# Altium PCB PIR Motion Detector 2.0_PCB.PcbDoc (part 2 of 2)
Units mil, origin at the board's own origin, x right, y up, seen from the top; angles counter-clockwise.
Board outline 6000 x 2200 mil, 4 copper layers (Layer 1 - Top Layer, Layer 2 - GND, Layer 3 - PWR, Layer 4 - Bottom Layer), stack 61.634 mil thick; 136 components, 49 nets, 322 pads, 287 vias.
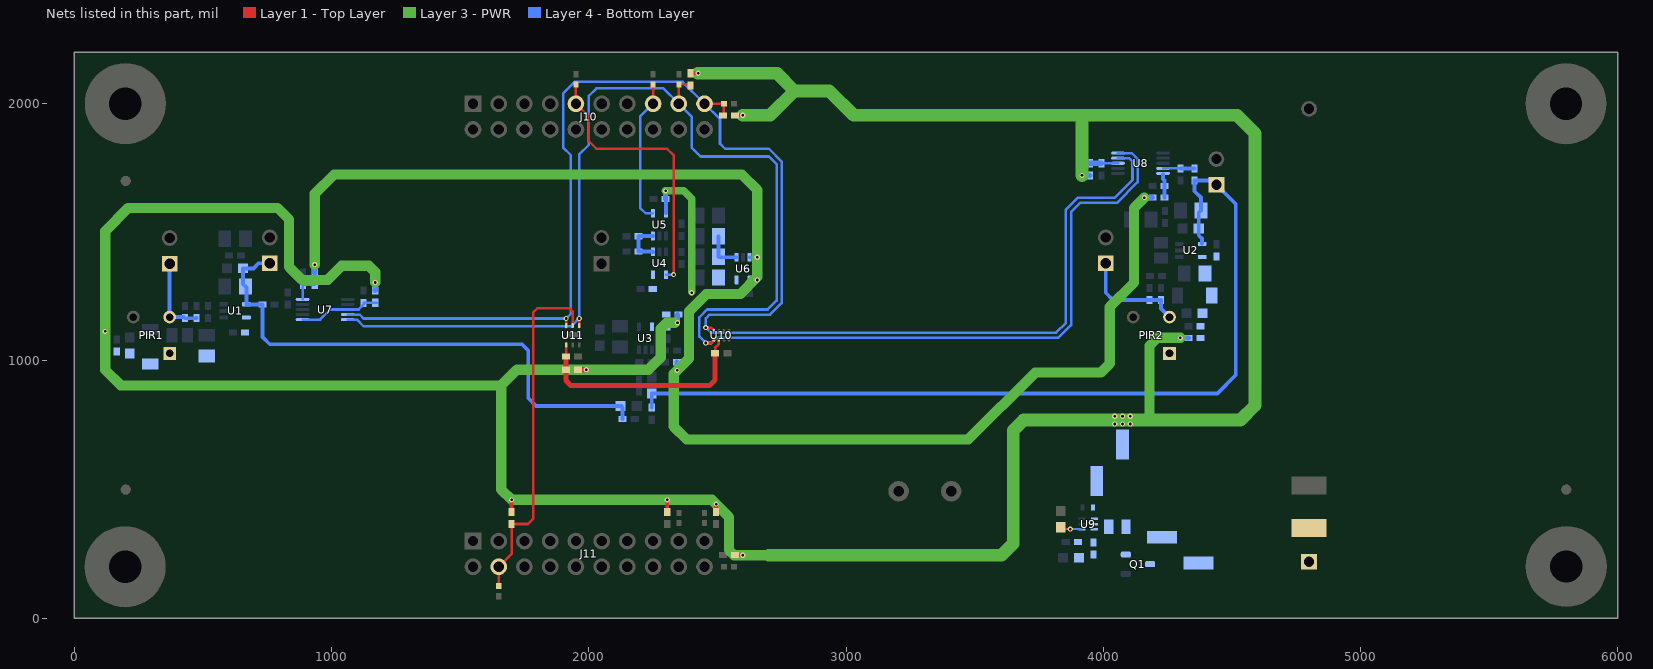
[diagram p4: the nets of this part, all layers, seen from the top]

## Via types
v1: diameter 20, hole 10, Layer 1 - Top Layer to Layer 4 - Bottom Layer, tented both sides, 286 vias
v2: diameter 19.68, hole 7.87, Layer 1 - Top Layer to Layer 4 - Bottom Layer, 1 vias

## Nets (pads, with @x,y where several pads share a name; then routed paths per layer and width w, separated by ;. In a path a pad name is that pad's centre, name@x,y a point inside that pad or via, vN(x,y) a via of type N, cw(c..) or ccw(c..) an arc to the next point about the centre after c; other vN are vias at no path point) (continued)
NetC14_1: C14.1 R23.2 U7.5 | length 102.6
  Layer 4 - Bottom Layer w10: U7.5@887.4,1239.37 887.4,1293.74 C14.1@889.67,1296.01 R23.2@934.67,1296.01
NetC15_1: C15.1 R24.2 U8.4 | length 122.6
  Layer 4 - Bottom Layer w10: U8.4@4232.56,1748.92 4232.85,1748.62 C15.1@4300,1748.62
  Layer 4 - Bottom Layer w15: C15.1@4300,1748.62 R24.2@4355,1748.62
NetC16_1: C16.1 R25.2 U8.5 | length 93.5
  Layer 4 - Bottom Layer w15: U8.5@4232.56,1726 4232.56,1707.44 4238.62,1701.38 C16.1@4238.62,1680 R25.2@4238.62,1635
NetC18_1: C18.1 R26.2 U9.3
NetC19_1: C19.1 J7.1 U9.1
NetC36_1: C36.1 R17.2 U4.1 U5.3 | length 172.2
  Layer 4 - Bottom Layer w15: U4.1@2249.41,1424.29 2248.7,1425 R17.2@2193.62,1425 C36.1@2193.62,1485 2194.33,1485.71 U5.3@2249.41,1485.71
NetJ1_1: J1.1 PIR1.2 R1.2 R2.1 | length 313.4
  Layer 4 - Bottom Layer w15: J1.1@370.57,1377.95 370.57,1170.85 PIR1.2@370.71,1170.71 425.67,1170.71 R1.2@430,1166.38 R2.1@475,1166.38
NetJ2_1: J2.1 PIR2.2 R7.2 R8.1 | length 421.1
  Layer 4 - Bottom Layer w15: J2.1@4010,1380 4010,1265 4038.62,1236.38 R8.1@4180,1236.38 R7.2@4225,1236.38 4225,1203.42 PIR2.2@4257.71,1170.71
NetJ6_2: J6.2 Q1.3
NetL1_2: L1.2 U9.2
NetR19_1: R19.1 R20.2 U6.1 | length 150.1
  Layer 4 - Bottom Layer w15: R20.2@2505,1485 R19.1@2505,1405 2506.56,1403.44 U6.1@2574.41,1403.44
NetR39_2: R39.2 U9.4 | length 85.9
  Layer 1 - Top Layer w8: R39.2@3835,353.5 3842.04,346.47 v1(3872.04,346.47)
  Layer 4 - Bottom Layer w8: v1(3872.04,346.47) U9.4@3917.99,346.47
OPT3002_INT: J11.4 R38.1 U11.5 U19.1 | length 1377.4
  Layer 1 - Top Layer w10: U19.1@1650,124.68 J11.4@1650,200 1700,250 R38.1@1700,366.38 1763.62,366.38 1785,387.76 1785,1190 1800,1205 1925,1205 1937.34,1192.66 U11.5@1937.34,1137.4
P3.3V: J7.2 R27.1 R28.1 R29.1 R30.1 R31.1 R32.1 R33.2 R34.2 R35.2 R36.2 R37.2 R38.2 | length 12934.7
  Layer 1 - Top Layer w15: R38.2@1700,413.62 v1(1700,460) ; R35.2@2305,413.62 v1(2305,460) ; R34.2@2395,2118.62 v1(2425,2118.62) ; R36.2@2495,413.62 v1(2495,443.62) ; R37.2@2568.62,245 v1(2598.62,245) ; R33.2@2568.62,1955 v1(2598.62,1955)
  Layer 1 - Top Layer w20: R32.1@1958.62,965.78 v1(1990,965.78)
  Layer 3 - PWR w40: v1(1170,1305) 1170,1345 1145,1370 1040,1370 985,1315 885,1315 835,1365 835,1550 790,1595 210,1595 120,1505 v1(120,1115) 120,965 180,905 1660,905 ; v1@2335,1148.62 2303.62,1148.62 2280,1125 2280,1015 2230.78,965.78 v1(1990,965.78) 1720.78,965.78 1660,905 ; 2700,245 v1(2598.62,245) 2565,245 2545,265 2545,393.62 v1(2495,443.62) 2478.62,460 v1(2305,460) v1(1700,460) 1660,500 1660,905 ; 4180,795 4180,1060 4210,1090 v1(4300,1090)
  Layer 3 - PWR w50: v1(2425,2118.62) 2731.38,2118.62 2800,2050 ; v1(2598.62,1955) 2705,1955 2800,2050 ; 2700,245 3605,245 3650,290 3650,730 3690,770 4533,770 4590,827 4590,1885 4520,1955 3030,1955 2935,2050 2800,2050 ; v1(3917.4,1721.38) 3917.4,1952.4
  Layer 4 - Bottom Layer w20: R27.1@120,1083.62 v1(120,1115) ; R28.1@1170,1273.62 v1(1170,1305) ; v1(2345,1148.62) R31.1@2345,1180 ; v1(3917.4,1721.38) R30.1@3948.78,1721.38 ; v1(4300,1090) R29.1@4331.38,1090
  other v1: 4045,755 4075,755 4105,755 4045,785 4075,785 4105,785
PIR1_OUT: C2.1 C4.2 J3.1 R5.2 R22.1 R40.2 U1.4 | length 2113.5
  Layer 4 - Bottom Layer w15: J3.1@760,1380 716.18,1380 696.18,1360 C2.1@656.5,1360 656.5,1298.5 R5.2@665,1290 669.29,1285.71 U1.4@669.29,1220.59 669.88,1220 R22.1@731.38,1220 731.38,1093.62 760,1065 1740,1065 1765,1040 1765,855 1794.53,825.47 C4.2@2126.95,825.47 ; C4.2@2123.5,825 2131.38,817.13 R40.2@2131.38,775
PIR2_OUT: C6.1 C8.2 J4.1 R11.2 R24.1 R41.2 U2.4 | length 3482.3
  Layer 4 - Bottom Layer w15: R41.2@2245,818.62 C8.2@2245,873.5 4443.5,873.5 4515,945 4515,1610 J4.1@4440,1685 4423.62,1701.38 R24.1@4355,1701.38 4355,1660 4380,1635 R11.2@4380,1585 4371.5,1576.5 C6.1@4371.5,1515 4371.5,1488.5 4384.29,1475.71 U2.4@4384.29,1455.59
PIR_OUT_HI: J10.9 U4.4 U21.1 | length 1087.5
  Layer 1 - Top Layer w10: U21.1@1950,2075.32 J10.9@1950,2000 2000,1950 2000,1855 2030,1825 2305,1825 2330,1800 v1(2330,1335.71)
  Layer 4 - Bottom Layer w10: U4.4@2300.59,1335.71 v1(2330,1335.71)
PIR_OUT_LO: J10.15 U5.4 U22.1 | length 559
  Layer 1 - Top Layer w10: J10.15@2250,2000 U22.1@2250,2075.32
  Layer 4 - Bottom Layer w10: U5.4@2249.41,1574.29 2220.71,1574.29 2200,1595 2200,1950 J10.15@2250,2000
SCL: J10.17 R34.1 U7.10 U8.10 U10.A1 U11.4 U15.1 | length 6267.3
  Layer 1 - Top Layer w10: U11.4@1962.93,1132 U11.4@1962.93,1137.4 v1(1962.93,1165) ; J10.17@2350,2000 U15.1@2350,2075.32 2391.06,2075.32 R34.1@2395,2071.38 ; v1(2455,1070) 2475.95,1070 U10.A1@2486.26,1080.32
  Layer 4 - Bottom Layer w10: U7.10@1062.6,1160.63 1099.37,1160.63 1125,1135 1932.93,1135 v1(1962.93,1165) 1962.93,1802.93 2000,1840 2000,2030 2029.84,2059.84 2290.16,2059.84 J10.17@2350,2000 2400,1950 2400,1830 2435,1795 2700,1795 2730,1765 2730,1235 2695,1200 2460,1200 2430,1170 2430,1095 v1(2455,1070) 2475.95,1070 2495.95,1090 3825,1090 3875,1140 3875,1580 3910,1615 4053.28,1615 4133.78,1695.5 4133.78,1785 4110.8,1807.98 U8.10@4057.36,1807.98
SDA: J10.19 R33.1 U7.9 U8.9 U10.A2 U11.6 U14.1 | length 6202.3
  Layer 1 - Top Layer w10: U11.6@1911.75,1132 U11.6@1911.75,1137.4 v1(1911.75,1165) ; J10.19@2450,2000 U14.1@2525.32,2000 2525.32,1958.94 R33.1@2521.38,1955 ; v1(2455,1130) 2475.95,1130 U10.A2@2486.26,1119.69
  Layer 4 - Bottom Layer w10: U7.9@1062.6,1180.32 1109.68,1180.32 1125,1165 v1(1911.75,1165) 1930,1183.25 1930,1800 1900,1830 1900,2039.84 1945.16,2085 2365,2085 J10.19@2450,2000 2510.04,1939.96 2510.04,1844.96 2530,1825 2700,1825 2750,1775 2750,1225 2705,1180 2470,1180 2455,1165 v1(2455,1130) 2475,1110 3816.72,1110 3855,1148.28 3855,1588.28 3901.72,1635 4045,1635 4113.78,1703.78 4113.78,1775 4100.49,1788.29 U8.9@4057.36,1788.29
VBAT: C17.1 L1.1 Q1.2 R26.1
VCC: BT1.1 J6.1 TP1.1
VCC1A: C20.1 C21.1 C22.1 C23.1 PIR1.1 R3.2 R27.2 U1.5
VCC1B: C24.1 R28.2 U7.1 U7.8 | length 318.2
  Layer 4 - Bottom Layer w10: U7.1@887.4,1160.63 955.63,1160.63 995,1200 U7.8@1062.6,1200 1105,1200 1125,1220 C24.1@1125,1226.01 R28.2@1175,1226.01
VCC2A: C25.1 C26.1 C27.1 C28.1 PIR2.1 R9.2 R29.2 U2.5
VCC2B: C29.1 R30.2 U8.8 | length 108.6
  Layer 4 - Bottom Layer w10: C29.1@3993.78,1768.62 U8.8@4057.36,1768.61
  Layer 4 - Bottom Layer w20: R30.2@3948.78,1768.62 C29.1@3993.78,1768.62
VCC3: C30.1 C31.1 C32.1 C33.1 R18.2 R31.2 U3.5 U4.5 U5.5 U6.5 | length 559.5
  Layer 3 - PWR w30: v1(2298.62,1661.38) 2368.62,1661.38 2400,1630 v1@2400,1270
  Layer 4 - Bottom Layer w15: U5.5@2300.59,1574.29 C31.1@2300.59,1628.03
  Layer 4 - Bottom Layer w20: C31.1@2298.62,1630 v1(2298.62,1661.38)
  other v1: 2400,1265
VCC4: C34.1 C35.1 R32.2 U10.B1 U11.1 | length 898.3
  Layer 1 - Top Layer w10: C34.1@1911.75,1020 U11.1@1911.75,1062.6 U11.1@1911.75,1068 ; C35.1@2491.38,1030 2491.38,1051.88 2505.95,1066.45 U10.B1@2505.95,1080.32
  Layer 1 - Top Layer w20: C34.1@1910.96,1017.21 1911.38,1016.79 R32.2@1911.38,965.78 1911.38,923.62 1930,905 2470,905 2491.38,926.38 C35.1@2491.38,1030
VREF: R16.1 R23.1 R25.1 U6.3 U6.4 | length 5874.8
  Layer 3 - PWR w40: v1(934.67,1374.63) 934.67,1649.67 1010,1725 2595,1725 2655,1665 v1(2655,1403.44) 2655,1326.65 2588.35,1260 2457,1260 2390,1193 2390,1010 2330,950 2330,745 2380,695 3475,695 3735,955 3990,955 4025,990 4025,1210 4120,1305 4120,1595 v1(4160,1635)
  Layer 4 - Bottom Layer w15: U6.4@2625.59,1314.86 v1(2655,1314.86) ; U6.3@2625.59,1403.44 v1(2655,1403.44)
  Layer 4 - Bottom Layer w20: R23.1@934.67,1343.25 v1(934.67,1374.63) ; v1(2343.62,963.62) R16.1@2343.62,995 ; v1(4160,1635) R25.1@4191.38,1635
pads on no net: FID1.1 FID2.1 FID3.1 FID4.1 FID5.1 FID6.1 H1.1 H2.1 H3.1 H4.1 J10.1 J10.2 J10.3 J10.5 J10.6 J10.7 J10.8 J10.10 J10.11 J10.12 J10.13 J10.14 J10.16 J10.18 J10.20 J11.1 J11.3 J11.5 J11.6 J11.7 J11.8 J11.9 J11.10 J11.11 J11.12 J11.13 J11.14 J11.15 J11.16 J11.18 U7.6 U7.7 U8.6 U8.7 U9.5 U10.C2

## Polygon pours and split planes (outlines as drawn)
GND on Layer 1 - Top Layer "Layer 1 - Top Layer - GND" (solid, remove dead copper, pour order 0): 20,20 5980,20 5980,2180 20,2180
GND on Layer 2 - GND "Layer 2 - GND" (solid, remove dead copper, pour order 2): 20,20 5980,20 5980,2180 20,2180
GND on Layer 3 - PWR "Layer 3 - PWR - GND" (solid, remove dead copper, pour order 4): 20,20 5980,20 5980,2180 20,2180
GND on Layer 4 - Bottom Layer "Layer 4 - Bottom Layer - GND" (solid, remove dead copper, pour order 6): 20,20 5980,20 5980,2180 20,2180

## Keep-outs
Keep-Out Layer:
  text ".Layer_Name" at 577,-858.49 h60

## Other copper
Layer 1 - Top Layer:
  pour cut-out: 2450,155.14 2350,155.14 2305.14,200 2305.14,255.14 2250,255.14 2250,315.32 2328.81,394.13 2450,394.13
  pour cut-out: 1605.14,200 1605.14,300 1644,300 1705,361 1788,361 1794.86,354.14 1794.86,200 1750,155.14 1650,155.14
  pour cut-out: 2350,1955.14 2405.14,1955.14 2405.14,1900 2494.86,1900 2494.86,2000 2450,2044.86 2380.86,2044.86 2350,2014
  pour cut-out: 1905.14,2000 1905.14,1900 1944,1900 2005,1839 2088,1839 2094.86,1845.86 2094.86,2000 2050,2044.86 1950,2044.86
  region net VCC: 4715,400 4715,210 4745,180 4855,180 4885,210 4885,400
  pour cut-out: 1810,990 2055,990 2055,1190 1810,1190
  pour cut-out: 2410,990 2655,990 2655,1180 2410,1180
  region net GND: 2520,1086 2520,993.13 2516.87,990 2594.61,990 2594.61,1041.39 2550,1086
  region net GND: 1928,1087 1932,1083 1932,1042 1942,1032 1942,1005 1950,997 1993.57,997 2010.57,980 2054,980 2060,986 2060,1113 1910,1113 1910,1087
  text ".Layer_Name" at 577,-858.49 h60
Layer 2 - GND:
  text ".Layer_Name" at 577,-858.49 h60
Layer 3 - PWR:
  text ".Layer_Name" at 577,-858.49 h60
Layer 4 - Bottom Layer:
  pour cut-out: 551.7,1241.42 551.7,1150.28 698.3,1150.28 698.3,1241.42
  pour cut-out: 2173.71,1014.81 2264.84,1014.81 2264.84,1161.41 2173.7,1161.41
  pour cut-out: 2228.58,1603.3 2319.72,1603.3 2319.72,1456.7 2228.58,1456.7
  pour cut-out: 2321.42,1306.7 2230.28,1306.7 2230.28,1453.3 2321.42,1453.3
  pour cut-out: 2646.42,1285.85 2555.28,1285.85 2555.28,1432.45 2646.42,1432.45
  pour cut-out: 4018.43,1707.58 4018.43,1828.61 4272,1828.61 4272,1707.58
  pour cut-out: 1095,1261.03 1095,1140 850,1140 850,1261.03
  pour cut-out: 2387.14,1855.14 2401,1869 2401,2013 2369.14,2044.86 1850,2044.86 1805.14,2000 1805.14,1900 1850,1855.14
  pour cut-out: 717.49,1422.51 702,1422.51 702,1431.5 695,1431.5 695,1417 717.49,1417
  region net GND: 155,1065 150,1070 150,1185 165,1200 315,1200 330,1185 330,1145 345,1130 400,1130 405,1125 405,1070 400,1065
  region net VCC1A: 95,1040 110,1055 625,1055 645,1075 645,1175 655,1185 690,1185 700,1175 700,985 675,960 110,960 95,975
  region net VCC: 4845,190 4825,170 4325,170 4310,185 4310,250 4330,270 4825,270 4845,250
  region net NetJ6_2: 4290,340 4290,215 4270,195 4165,195 4145,215 4145,340 4165,360 4270,360
  region net VBAT: 3880,255 3890,265 4045,265 4065,285 4065,380 4075,390 4110,390 4120,380 4120,240 4090,210 3886,210 3880,216
  region net NetC18_1: 3882,286 3890,278 3977,278 3985,286 3985,347 3980,352 3951,352 3946,347 3946,330 3937,321 3890,321 3882,313
  region net NetL1_2: 3986,372 3998,384 4041,384 4045,380 4045,330 4041,326 4001,326 3997,330 3997,349 3986,360 3951,360 3948,363 3948,369 3951,372
  region net NetC19_1: 3980,380 4010,410 4010,594 4004,600 3951,600 3945,594 3945,383 3948,380
  region net GND: 3931,380 3934,383 3934,461 3925,470 3850,470 3840,460 3840,400 3850,390 3878,390 3888,380
  region net VCC2A: 4220,1045 4235,1060 4345,1060 4360,1075 4360,1405 4380,1425 4470,1425 4490,1405 4490,995 4455,960 4235,960 4220,975
  region net GND: 2475,1530 2550,1530 2560,1540 2560,1590 2550,1600 2475,1600
  region net VCC3: 2230,1120 2235,1115 2315,1115 2320,1120 2320,1200 2340,1220 2580,1220 2595,1235 2595,1344.46 2580.31,1359.15 2479.15,1359.15 2470,1350 2470,1290 2455,1275 2285,1275 2270,1290 2270,1345 2260,1355 2240,1355 2230,1345
  region net P3.3V: 4045,800 4025,780 4025,625 4035,615 4115,615 4125,625 4125,780 4105,800
  region net GND: 4205,1295 4215,1305 4276,1305 4286,1295 4330,1295 4350,1275 4350,1125 4345,1120 4300,1120 4290,1130 4290,1140 4300,1150 4300,1185 4265,1220 4265,1250 4250,1265 4215,1265 4205,1275
  text ".Layer_Name" at 577,-858.49 h60

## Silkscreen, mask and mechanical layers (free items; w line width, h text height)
Top Overlay:
  region: 5825,1600 5825,1300 5925,1300 5925,1600
  text "'.PRJ_Number'.PCB_Rev-" at 5900,600 h108.27 r90
  text "GND" at 4943,448.03 h72.83 r90
  text "VCC" at 4943,283.03 h72.83 r90
  text ".Layer_Name" at 577,-858.49 h60
Bottom Overlay:
  text "SDA" at 2465,2165 h50 r90
  text "P.O" at 1940,2160 h50 r90
  text "P.O" at 2245,2160 h50 r90
  text "SCL" at 2365,2160 h50 r90
  text "LO" at 2285,2150 h50 r90
  text "HI" at 1980,2145 h50 r90
  text "GND" at 1665,1825 h50 r90
  text "ADC_A_2" at 2465,575 h50 r90
  text "ADC_A_1" at 2365,570 h50 r90
  text "GND" at 1565,125 h50 r90
  text "HDC" at 1665,125 h50 r90
  text "OPT" at 2465,125 h50 r90
  text ".Layer_Name" at 577,-858.49 h60
Top Paste:
  text ".Layer_Name" at 577,-858.49 h60
Bottom Paste:
  text ".Layer_Name" at 577,-858.49 h60
Top Solder:
  text ".Layer_Name" at 577,-858.49 h60
  text ".Layer_Name" at 577,-858.49 h60
Bottom Solder:
  text ".Layer_Name" at 577,-858.49 h60
Drill Guide:
  text ".Layer_Name" at 577,-858.49 h60
M1 Board Outline:
  the board outline again, w10
  text ".Layer_Name" at 577,-858.49 h60
M2 Board Dimensions:
  rectangle: 0,-275 125,-150
  rectangle: 125,-400 500,-275
  lines w7: 0,-275 1000,-275 ; 125,-400 125,-150 ; 250,-400 250,-150 ; 500,-400 500,-150 ; 750,-400 750,-150 ; 0,-400 1000,-400 1000,-150 0,-150 0,-400
  text ".Layer_Name" at 577,-858.49 h60
M3 3D STEP Top:
  text ".Layer_Name" at 577,-858.49 h60
M4 3D STEP Bottom:
  text ".Layer_Name" at 577,-858.49 h60
M5 Assembly Top:
  lines w10: -292,-930.17 6308,-930.17 ; -292,-726.83 6310,-726.83 ; -292,-523.5 -292,-1133.5 3713,-1133.5 6310,-1133.5 6310,-523.5 -291.5,-523.5 -291.5,-1133.5 1284,-1133.5 ; 2173,-1133.5 2173,-523.5 ; 3440,-726.83 3440,-523.5 ; 4280,-726.83 4280,-523.5 ; 4902,-1140 4902,-937.17
  text "COMPONENTS MARKED 'DNP' SHOULD NOT BE POPULATED." at 1153.5,-318.5 h60
  text "ASSEMBLY VARIANT:" at 1153,-434 h60
  text ".VariantName" at 2189,-434 h60
  text "PCB VIEWED FROM TOP SIDE" at -228.5,-655.67 h60
  text "BOARD #:" at 2248,-655.67 h60
  text ".PRJ_Number" at 2793.5,-655.67 h60
  text "REV:" at 3638,-655.67 h60
  text ".PCB_Rev" at 3929.5,-655.67 h60
  text "SVN REV:" at 4476,-655.67 h60
  text ".VersionControl_RevNumber" at 4982,-655.67 h60
  text "TID #:" at 2248,-859 h60
  text ".TID" at 2793.5,-859 h60
  text "PLOT NAME =" at -228.5,-1064.34 h60
  text ".plot_File_Name" at 577,-1064.34 h60
  text "GENERATED    :" at 2250,-1064.34 h60
  text ".Print_Date" at 3119.5,-1064.34 h60
  text ".Print_Time" at 3848.5,-1064.34 h60
  text "TEXAS INSTRUMENTS" at 5113,-1064.34 h60
M6 Assembly Bottom:
  lines w10: -292.5,-727.33 6309.5,-727.33 ; -290.5,-930.67 6309.5,-930.67 ; 1115.5,-1140.5 1115.5,-937.67 ; 1737.5,-727.33 1737.5,-524 ; 2577.5,-727.33 2577.5,-524 ; 3844.5,-1134 3844.5,-524 ; 4733.5,-1134 6309,-1134 6309,-524 -292.5,-524 -292.5,-1134 2304.5,-1134 6309.5,-1134 6309.5,-524
  text "COMPONENTS MARKED 'DNP' SHOULD NOT BE POPULATED." at 6102,-318 h60
  text ".VariantName" at 5058,-434 h60
  text "ASSEMBLY VARIANT:" at 6097,-434 h60
  text ".VersionControl_RevNumber" at 1035.5,-656.17 h60
  text "SVN REV:" at 1541.5,-656.17 h60
  text ".PCB_Rev" at 2088,-656.17 h60
  text "REV:" at 2379.5,-656.17 h60
  text ".PRJ_Number" at 3224,-656.17 h60
  text "BOARD #:" at 3769.5,-656.17 h60
  text "PCB VIEWED FROM BOTTOM SIDE" at 6246,-656.17 h60
  text ".TID" at 3224,-859.5 h60
  text "TID #:" at 3769.5,-859.5 h60
  text "TEXAS INSTRUMENTS" at 904.5,-1064.84 h60
  text ".Print_Time" at 2169,-1064.84 h60
  text ".Print_Date" at 2898,-1064.84 h60
  text "GENERATED    :" at 3767.5,-1064.84 h60
  text ".plot_File_Name" at 5440.5,-1064.84 h60
  text "PLOT NAME =" at 6246,-1064.84 h60
M9 Title Sheet:
  drawing of 1178 lines, arcs and shapes, not listed
  text "1" at 739.84,8036.5 h70
  text "2" at 3235.5,8036.5 h70
  text "3" at 5724.84,8036.5 h70
  text "4" at 8231.51,8036.5 h70
  text "5" at 10730.5,8036.5 h70
  text "6" at 13235.5,8036.5 h70
  text "A" at -416.5,6893.5 h70
  text "A" at 14383.5,6893.5 h70
  text "B" at -416.5,4513.5 h70
  text "B" at 14383.5,4513.5 h70
  text "C" at -416.5,2138.5 h70
  text "C" at 14383.5,2138.5 h70
  text "PROJECT TITLE:" at 11343.5,277.5 h45
  text ".PRJ_Title" at 11393.5,144.17 h70
  text "DESIGNED FOR:" at 11343.5,-23.5 h45
  text ".PRJ_Customer" at 11393.5,-163.5 h70
  text "D" at -416.5,-231.5 h70
  text "D" at 14383.5,-231.5 h70
  text "FILE NAME:" at 11343.5,-323.5 h45
  text ".PCB_File_Name_No_Path" at 11393.5,-443.5 h70
  text "Texas Instruments (TI) and/or its licensors do not warrant the accuracy or completeness of this specification" at 6374,-605.34 h45
  text "ENGINEER:" at 11343.5,-613.5 h45
  text "LAYOUT BY:" at 12848.5,-613.5 h45
  text "or any information contained therein. TI and/or its licensors do not warrant that this design will meet" at 6329.01,-718 h45
  text ".PRJ_Engineer" at 11393.5,-768.49 h70
  text "JMM" at 12856.28,-803.5 h100
  text "s  o  l  u  t  i  o  n  s" at 13714.28,-806.5 h68
  text "the specifications, will be suitable for your application or fit for any particular purpose, or will operate in" at 6329.01,-830.67 h45
  text ".Layer_Name" at 577,-858.49 h60
  text "ALTIUM DESIGNER VERSION:" at 12848.5,-923.5 h45
  text "an implementation. TI and/or its licensors do not warrant that the design is production worthy. You should" at 6329.01,-943.33 h45
  text "completely validate and test your design implementation to confirm the system functionality for your application." at 6374,-1056 h45
  text ".print_Scale" at 11393.5,-1056.83 h70
  text ".Application_BuildNumber" at 12899,-1056.83 h70
  text "1" at 739.84,-1263.5 h70
  text "2" at 3235.5,-1263.5 h70
  text "3" at 5724.84,-1263.5 h70
  text "4" at 8231.51,-1263.5 h70
  text "5" at 10730.5,-1263.5 h70
  text "6" at 13235.5,-1263.5 h70
M10 Fab Notes:
  drawing of 173 lines, arcs and shapes, not listed
  text "DESIGN INFORMATION" at 12378.02,6201 h60
  text "MIN. TRACK WIDTH:" at 11733.46,6021 h60
  text "MIL" at 12984.46,6021 h60
  text "10" at 12805,6020 h60
  text "MIN. CLEARANCE:" at 11733.46,5889 h60
  text "0.2" at 12769.7,5889 h60
  text "mm" at 12984.46,5889 h60
  text "MIN. VIA PAD SIZE:" at 11733.46,5757 h60
  text "20" at 12799.71,5757 h60
  text "MIL" at 12984.46,5757 h60
  text "0.05mm (2MIL)" at 12428.46,5615.29 h60
  text "MINIMUM ANNULAR RING" at 11404.23,5611 h60
  text "EXTERNAL" at 13136.46,5611 h60
  text "PER" at 11604.23,5493 h60
  text "IPC-D-275 CLASS 2 LEVEL C" at 11824.23,5493 h60
  text "MIL, HOLES" at 13312.46,5380.71 h60
  text "+/-" at 12920,5380 h60
  text "+/-" at 13774,5380 h60
  text "REGISTRATION TOLERANCES:" at 11404.23,5375 h60
  text "METAL" at 12604,5375 h60
  text "5" at 13180.2,5375 h60
  text "3" at 14013.2,5375 h60
  text "MIL" at 14129.46,5375 h60
  text "+/-" at 13774,5262 h60
  text "HOLE SIZE TOLERANCE (UNLESS OTHERWISE SPECIFIED):" at 11404.23,5257 h60
  text "3" at 14013.2,5257 h60
  text "MIL" at 14129.46,5257 h60
  text "MATERIAL:" at 11329.46,5047.54 h60
  text "FR-4 High Tg" at 12315.9,4907.21 h60
  text "FR-408" at 11750.46,4898.64 h60
  text "OTHER" at 13238.46,4898.64 h60
  text "X" at 12161,4895 h60
  text "62 MIL (1.6mm) +/-10%" at 12070.56,4735.92 h60
  text "THICKNESS:" at 11404.23,4731.64 h60
  text "X" at 11942.4,4731.64 h60
  text "OTHER" at 13355.46,4731.64 h60
  text "TOLERANCE:" at 11404.23,4573.64 h60
  text "X" at 12243.53,4573.64 h60
  text "ANSI IPC-6012 TYPE 3 CLASS 2" at 12430.48,4573.64 h60
  text "OTHER +/-" at 12430.46,4417.64 h60
  text "BOW & TWIST:" at 11404.23,4260.64 h60
  text "X" at 12243.53,4260.64 h60
  text "ANSI IPC-6012 TYPE 3 CLASS 2" at 12430.48,4260.64 h60
  text "OTHER +/-" at 12430.46,4102.13 h60
  text "DRILLING:" at 11329.46,3963.64 h60
  text "REFERENCE:" at 11404.23,3846.64 h60
  text "X" at 12052.46,3846.64 h60
  text "AS SHOWN" at 12239.46,3846.64 h60
  text "X" at 12953.46,3846.64 h60
  text "NC_DRILL FILES" at 13090.46,3846.64 h60
  text "PTH COPPER THICKNESS:" at 11404.23,3688.64 h60
  text "X" at 12534.46,3688.64 h60
  text "20-30 um" at 12671.46,3688.64 h60
  text "OTHER" at 13388.46,3688.64 h60
  text "BOARD FINISH:" at 11329.46,3529.64 h60
  text "SILKSCREEN:" at 11484.68,3411.64 h60
  text "X" at 12433.46,3411.64 h60
  text "TOP" at 12559.46,3411.64 h60
  text "X" at 12943.46,3411.64 h60
  text "BOTTOM" at 13070.46,3411.64 h60
  text "SILKSCREEN COLOR:" at 11484.68,3244.64 h60
  text "X" at 12432.42,3244.64 h60
  text "WHITE" at 12559.46,3244.64 h60
  text "OTHER" at 13070.46,3244.64 h60
  text "X" at 12563.42,3085.44 h60
  text "GREEN" at 12690.46,3085.44 h60
  text "OTHER" at 13308.46,3085.44 h60
  text "SOLDER RESIST COLOR:" at 11484.68,3074.64 h60
  text "X" at 12563.42,2915.44 h60
  text "MATTE" at 12690.46,2915.44 h60
  text "SEMI-GLOSS" at 13308,2914.8 h60
  text "IMMERSION GOLD (ENIG)" at 12390.46,2726.92 h60
  text "ENEPIG" at 13728,2723.64 h60
  text "SURFACE FINISH:" at 11329.46,2722.64 h60
  text "X" at 12203.51,2722.64 h60
  text "IMM. TIN/SILVER OR EQUIV" at 11659,2565.64 h60
  text "OTHER" at 13090.46,2565.64 h60
  text "ARRAY/PANEL:" at 11329.46,2386.64 h60
  text "CUT AND TRIM PER M1 BOARD OUTLINE" at 12390.46,2382.35 h60
  text "N.C. ROUTE" at 12390.46,2230.64 h60
  text "X" at 13069.46,2230.64 h60
  text "V. SCORE" at 13256.46,2230.64 h60
  text "CERTIFICATION:" at 11329.46,2093.64 h60
  text "MATERIALS AND WORKMANSHIP FOR ALL PCBS" at 12054.46,2093.64 h60
  text "TO MEET OR EXCEED THE REQUIREMENTS OF:" at 12054.46,1995.64 h60
  text "X" at 11680.96,1859.13 h60
  text "ANSI IPC-A-600F CLASS ->" at 11819.96,1859.13 h60
  text "X" at 13459.02,1859.13 h60
  text "2" at 13577.96,1859.14 h60
  text "1" at 13262.96,1857.64 h60
  text "3" at 13931.96,1857.64 h60
  text "X" at 12495.02,1699.64 h60
  text "RoHS" at 12631.96,1699.64 h60
  text "OTHER" at 13276.36,1699.64 h60
  text "PER ORDER" at 13673.42,1699.64 h60
  text "ALL BOARDS MUST MEET OR EXCEED UL94-V0 REQUIREMENTS." at 11357,1534 h60
  text "PCB MUST BEAR THE UL94V-0 UL REGISTERED MATERIAL ID NUMBER" at 11357,1414 h60
  text "ADDITIONAL REQUIREMENTS:" at 11329.46,1240.64 h60
  text "MICROSECTION:" at 11404.23,1125.64 h60
  text "YES" at 12309.96,1125.64 h60
  text "REQUIRED" at 13171.46,969.49 h60
  text "BARE BOARD ELEC. TEST:" at 11404.23,966.64 h60
  text "NONE" at 12709.96,966.64 h60
  text "X" at 13044.46,966.64 h60
  text "PER ORDER" at 13763.46,966.64 h60
  text ".Layer_Name" at 577,-858.49 h60
M11 Gerber Information:
  lines w10: -292,-930.17 6308,-930.17 ; -292,-726.83 6310,-726.83 ; -292,-523.5 -292,-1133.5 3713,-1133.5 6310,-1133.5 6310,-523.5 -291.5,-523.5 -291.5,-1133.5 1284,-1133.5 ; 2173,-1133.5 2173,-523.5 ; 3440,-726.83 3440,-523.5 ; 4280,-726.83 4280,-523.5 ; 4902,-1140 4902,-937.17
  text "ALL ARTWORK VIEWED FROM TOP SIDE" at -228.5,-655.67 h60
  text "BOARD #:" at 2248,-655.67 h60
  text ".PRJ_Number" at 2793.5,-655.67 h60
  text "REV:" at 3638,-655.67 h60
  text ".PCB_Rev" at 3929.5,-655.67 h60
  text "SVN REV:" at 4476,-655.67 h60
  text ".VersionControl_RevNumber" at 4982,-655.67 h60
  text "LAYER NAME =" at -228.5,-858.49 h60
  text "TID #:" at 2248,-859 h60
  text ".TID" at 2793.5,-859 h60
  text "PLOT NAME =" at -228.5,-1064.34 h60
  text ".plot_File_Name" at 577,-1064.34 h60
  text "GENERATED    :" at 2250,-1064.34 h60
  text ".Print_Date" at 3119.5,-1064.34 h60
  text ".Print_Time" at 3848.5,-1064.34 h60
  text "TEXAS INSTRUMENTS" at 5113,-1064.34 h60
M12 Stackup:
  drawing of 295 lines, arcs and shapes, not listed
  text "Layer" at 9282.5,7812.5 h60
  text "Name" at 9692.41,7812.5 h60
  text "Material" at 11102,7812.5 h60
  text "Thickness" at 11961.77,7812.5 h60
  text "Constant" at 12611.6,7812.5 h60
  text "Board Layer Stack" at 13181.47,7812.5 h60
  text "1" at 9282.5,7692.5 h60
  text "Top Overlay" at 9692.41,7692.5 h60
  text "2" at 9282.5,7572.5 h60
  text "Top Solder" at 9692.41,7572.5 h60
  text "Solder Resist" at 11102,7572.5 h60
  text "0.40mil" at 11961.77,7572.5 h60
  text "3.5" at 12611.6,7572.5 h60
  text "3" at 9282.5,7452.5 h60
  text "Layer 1 - Top Layer" at 9692.41,7452.5 h60
  text "Copper" at 11102,7452.5 h60
  text "1.40mil" at 11961.77,7452.5 h60
  text "4" at 9282.5,7332.5 h60
  text "Dielectric 1" at 9692.41,7332.5 h60
  text "FR-4" at 11102,7332.5 h60
  text "7.00mil" at 11961.77,7332.5 h60
  text "4.2" at 12611.6,7332.5 h60
  text "5" at 9282.5,7212.5 h60
  text "Layer 2 - GND" at 9692.41,7212.5 h60
  text "Copper" at 11102,7212.5 h60
  text "1.42mil" at 11961.77,7212.5 h60
  text "6" at 9282.5,7092.5 h60
  text "Dielectric 2" at 9692.41,7092.5 h60
  text "FR-4" at 11102,7092.5 h60
  text "42.00mil" at 11961.77,7092.5 h60
  text "4.2" at 12611.6,7092.5 h60
  text "7" at 9282.5,6972.5 h60
  text "Layer 3 - PWR" at 9692.41,6972.5 h60
  text "Copper" at 11102,6972.5 h60
  text "1.42mil" at 11961.77,6972.5 h60
  text "8" at 9282.5,6852.5 h60
  text "Dielectric 3" at 9692.41,6852.5 h60
  text "FR-4" at 11102,6852.5 h60
  text "7.00mil" at 11961.77,6852.5 h60
  text "4.2" at 12611.6,6852.5 h60
  text "9" at 9282.5,6732.5 h60
  text "Layer 4 - Bottom Layer" at 9692.41,6732.5 h60
  text "Copper" at 11102,6732.5 h60
  text "1.40mil" at 11961.77,6732.5 h60
  text "10" at 9282.5,6612.5 h60
  text "Bottom Solder" at 9692.41,6612.5 h60
  text "Solder Resist" at 11102,6612.5 h60
  text "0.40mil" at 11961.77,6612.5 h60
  text "3.5" at 12611.6,6612.5 h60
  text "11" at 9282.5,6492.5 h60
  text "Bottom Overlay" at 9692.41,6492.5 h60
  text ".Layer_Name" at 577,-858.49 h60
M13 Component Bodies Top:
  text ".Layer_Name" at 577,-858.49 h60
M14 Component Bodies Bottom:
  text ".Layer_Name" at 577,-858.49 h60
M15 Courtyards Top:
  text ".Layer_Name" at 577,-858.49 h60
M16 Courtyards Bottom:
  text ".Layer_Name" at 577,-858.49 h60
Drill Drawing:
  circle w10: c6458.72,209.68 r27.63
  lines w10: 6431.09,320.19 6444.9,320.19 6444.9,306.38 6472.53,306.38 6472.53,320.19 6486.34,320.19 6486.34,347.82 6472.53,347.82 6472.53,361.63 6444.9,361.63 6444.9,347.82 6431.09,347.82 6431.09,320.19 ; 6431.09,430.7 6486.34,430.7 6486.34,485.95 6431.09,485.95 6431.09,430.7 ; 6431.09,555.02 6486.34,555.02 6486.34,610.27 6431.09,610.27 6431.09,555.02 ; 6431.09,734.59 6486.34,734.59 6458.72,679.34 6431.09,734.59 ; 6431.09,803.66 6431.09,817.47 6444.9,831.28 6431.09,845.1 6431.09,858.91 6444.9,858.91 6458.72,845.1 6472.53,858.91 6486.34,858.91 6486.34,845.1 6472.53,831.28 6486.34,817.47 6486.34,803.66 6472.53,803.66 6458.72,817.47 6444.9,803.66 6431.09,803.66 ; 6442.14,441.75 6475.29,441.75 6475.29,474.9 6442.14,474.9 6442.14,441.75
  lines w12: 6381,144.76 10081.13,144.76 ; 6381,890.68 10081.13,890.68 ; 6718.86,20.44 6718.86,1015 ; 7050.86,20.44 7050.86,1015 ; 7687.43,20.44 7687.43,1015 ; 7946.57,20.44 7946.57,1015 ; 8321.72,20.44 8321.72,1015 ; 9514.7,20.44 9514.7,1015 ; 6381,20.44 10081.13,20.44 10081.13,1015 6381,1015 6381,20.44
  text "Symbol" at 6455.59,927.98 h72
  text "Quantity" at 6756.16,927.98 h72
  text "Finished Hole Size" at 7088.16,927.98 h72
  text "Plated" at 7724.72,927.98 h72
  text "Hole Type" at 7983.86,927.98 h72
  text "Drill Layer Pair" at 8359.02,927.98 h72
  text "Hole Tolerance" at 9551.99,927.98 h72
  text "1" at 6756.16,803.66 h60
  text "7,87mil (0,200mm)" at 7088.16,803.66 h60
  text "PTH" at 7724.72,803.66 h60
  text "Round" at 7983.86,803.66 h60
  text "Layer 1 - Top Layer - Layer 4 - Bottom Layer" at 8359.02,803.66 h60
  text "286" at 6756.16,679.34 h60
  text "10,00mil (0,254mm)" at 7088.16,679.34 h60
  text "PTH" at 7724.72,679.34 h60
  text "Round" at 7983.86,679.34 h60
  text "Layer 1 - Top Layer - Layer 4 - Bottom Layer" at 8359.02,679.34 h60
  text "6" at 6756.16,555.02 h60
  text "29,53mil (0,750mm)" at 7088.16,555.02 h60
  text "PTH" at 7724.72,555.02 h60
  text "Round" at 7983.86,555.02 h60
  text "Layer 1 - Top Layer - Layer 4 - Bottom Layer" at 8359.02,555.02 h60
  text "42" at 6756.16,430.7 h60
  text "40,00mil (1,016mm)" at 7088.16,430.7 h60
  text "PTH" at 7724.72,430.7 h60
  text "Round" at 7983.86,430.7 h60
  text "Layer 1 - Top Layer - Layer 4 - Bottom Layer" at 8359.02,430.7 h60
  text "12" at 6756.16,306.38 h60
  text "40,16mil (1,020mm)" at 7088.16,306.38 h60
  text "PTH" at 7724.72,306.38 h60
  text "Round" at 7983.86,306.38 h60
  text "Layer 1 - Top Layer - Layer 4 - Bottom Layer" at 8359.02,306.38 h60
  text "4" at 6756.16,182.06 h60
  text "125,98mil (3,200mm)" at 7088.16,182.06 h60
  text "PTH" at 7724.72,182.06 h60
  text "Round" at 7983.86,182.06 h60
  text "Layer 1 - Top Layer - Layer 4 - Bottom Layer" at 8359.02,182.06 h60
  text "351 Total" at 6756.16,57.74 h60
  text ".Layer_Name" at 577,-858.49 h60
M17 Embedded Cavity:
  text ".Layer_Name" at 577,-858.49 h60
M18 Embedded Assembly:
  text ".Layer_Name" at 577,-858.49 h60
M19 Embedded Keepout:
  text ".Layer_Name" at 577,-858.49 h60

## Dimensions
0,-400 to 1000,-400 on M2 Board Dimensions
0,0 to 0,2200 on M2 Board Dimensions
0,0 to 6000,0 on M2 Board Dimensions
